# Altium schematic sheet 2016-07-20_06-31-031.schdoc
size 229 x 134 mm; SheetNumber: 1; SheetTotal: 1
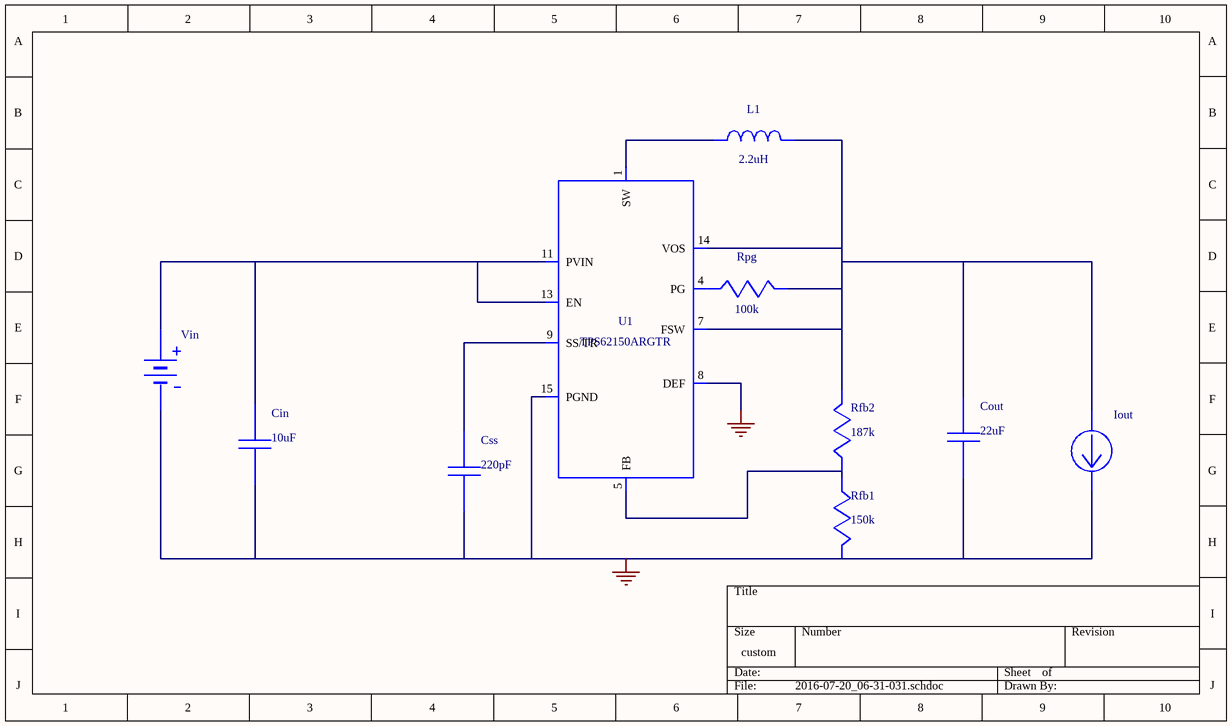
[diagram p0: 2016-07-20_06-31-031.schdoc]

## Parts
Cin  value 10uF  (hidden comment: LMK212BJ106KG-T)
Cout  value 22uF  (hidden comment: GRM21BR60J226ME39L)
Css  value 220pF  (hidden comment: GRM033R71C221KA01D)
Iout  WB_CURRENT_LOAD  (value not drawn)
L1  value 2.2uH  (hidden comment: IHLP1212BZER2R2M11)
Rfb1  value 150k  (hidden comment: CRCW0402150KFKED)
Rfb2  value 187k  (hidden comment: CRCW0402187KFKED)
Rpg  value 100k  (hidden comment: CRCW0402100KFKED)
U1  TPS62150ARGTR
Vin  WB_BATTERY  (value not drawn)

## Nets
0: Cin.2 Cout.2 Css.2 Iout.2(-) Rfb1.1 U1.6(AGND) U1.8(DEF) U1.15(PGND) U1.16(PGND) U1.17(ETPAD) Vin.2(-)
NetCin_1: Cin.1 U1.10(AVIN) U1.11(PVIN) U1.12(PVIN) U1.13(EN) Vin.1(+)
NetCout_1: Cout.1 Iout.1(+) L1.2 Rfb2.1 Rpg.1 U1.7(FSW) U1.14(VOS)
NetCss_1: Css.1 U1.9(SS/TR)
NetL1_1: L1.1 U1.1(SW) U1.2(SW) U1.3(SW)
NetRfb1_2: Rfb1.2 Rfb2.2 U1.5(FB)
NetRpg_2: Rpg.2 U1.4(PG)

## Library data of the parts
Cin = LMK212BJ106KG-T: Manufacturer Name: Taiyo Yuden
Cout = GRM21BR60J226ME39L: GRM21BR60J226ME3; Manufacturer Name: MuRata
Css = GRM033R71C221KA01D: GRM033R71C221KA0; Manufacturer Name: MuRata
L1 = IHLP1212BZER2R2M11: Unknown; Manufacturer Name: Vishay-Dale
Rfb1 = CRCW0402150KFKED: Manufacturer Name: Vishay-Dale
Rfb2 = CRCW0402187KFKED: Manufacturer Name: Vishay-Dale
Rpg = CRCW0402100KFKED: Manufacturer Name: Vishay-Dale
U1 = TPS62150ARGTR: Manufacturer Name: Texas Instruments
